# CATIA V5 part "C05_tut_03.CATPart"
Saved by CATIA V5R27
Part number: Part1
Bounding box of the stored display mesh (mm): x -75 to 75, y -149.983 to 149.983, z 0 to 150
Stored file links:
  E:\_Deepak\2017_Deepak\CATIA\Resources\Tutorial Files\Tutorials\c05_catia_v5_6r2016_tut\C05_tut_03.CATPart
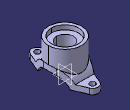
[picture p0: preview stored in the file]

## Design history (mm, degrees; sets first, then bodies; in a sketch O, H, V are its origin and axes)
Body1 (main body)
  Sketch1 on yz-plane, origin (0, 0, 0), H (0, 1, 0), V (0, 0, 1)
    point P1 (-150, 0)
    line L1 (-150, 0) -> (-74.162, 0)
    line L2 (150, 0) -> (150, 25)
    line L3 (150, 25) -> (89.4427, 25)
    line L4 (-150, 25) -> (-150, 0)
    point P2 (150, 0)
    arc A1 centre (0, -30) radius 80 from (74.162, 0) to (-74.162, 0) ccw
    point P5 (0, -30)
    arc A2 centre (0, -30) radius 105 from (89.4427, 25) to (-89.4427, 25) ccw
    line L5 (74.162, 0) -> (150, 0)
    line L6 (-89.4427, 25) -> (-150, 25)
    length L2 = 25
    distance V L4 = 150
    distance L1 P5 = 30
    radius A1 = 80
    radius A2 = 105
    distance P1 P2 = 300
    coincidence: P1 H, P5 V, L1 L5, L3 L6
    horizontal: L1 H, L3 H, L5 H, L6 H
    vertical: L2 V, L4 V
  Pad1: profile Sketch1, direction (1, 0, 0), length 75, mirrored extent
  Sketch2 on xy-plane, origin (0, 0, 0), H (1, 0, 0), V (0, 1, 0)
    arc A1 centre (0, 0) radius 75 from (-68.7386, 30) to (-68.7386, -30) ccw
    arc A2 centre (0, 125) radius 25 from (22.9129, 135) to (-22.9129, 135) ccw
    point P1 (0, 125)
    reference intersected line E1 through (0, 0) direction (-1, 0) from zx-plane
    arc A3 centre (0, -125) radius 25 from (22.9129, -135) to (-22.9129, -135) cw
    line L1 (-22.9129, 135) -> (-68.7386, 30)
    line L2 (22.9129, 135) -> (68.7386, 30)
    line L3 (-68.7386, -30) -> (-22.9129, -135)
    line L4 (22.9129, -135) -> (68.7386, -30)
    point P12 (68.7386, -30)
    arc A4 centre (0, 0) radius 75 from (68.7386, -30) to (68.7386, 30) ccw
    reference projected line E2 (-75, 89.4427) -> (-75, -89.4427) from edge [start face of Pad1 | face of Pad1 from Sketch1.A2]
    reference projected line E3 (-75, 150) -> (75, 150) from edge [face of Pad1 from Sketch1.L3 | face of Pad1 from Sketch1.L2]
    radius A2 = 25
    coincidence: P1 V, A1 P12, A1 A4
    symmetry: A2 A3 E1
    tangency: L1 A2, L1 A1, L2 A2, L2 A1, L3 A1, L3 A3, L4 A3, L4 A1, A1 E2, A2 E3
  Pocket1: profile Sketch2, direction (0, 0, -1), length 83, mirrored extent, outer side
  Plane1: type Offset, RefPlane xy-plane, Offset 150
  Sketch3 on Plane1, origin (0, 0, 150), H (1, 0, 0), V (0, 1, 0)
    circle A1 centre (0, 0) radius 75
    radius A1 = 75
  Pad2: profile Sketch3, direction (0, 0, 1), up to face of Pad1 from Sketch1.A2
  Sketch4 on yz-plane, origin (0, 0, 0), H (0, 1, 0), V (0, 0, 1)
    point P1 (0, 150)
    line L1 (0, 150) -> (0, 0)
    line L2 (0, 0) -> (37.5, 0)
    line L3 (37.5, 0) -> (37.5, 130)
    line L4 (37.5, 130) -> (61.5, 130)
    line L5 (61.5, 130) -> (61.5, 150)
    line L6 (61.5, 150) -> (0, 150)
    reference projected line E1 (-75, 150) -> (75, 150) from edge [face of Pad2 from Sketch3.A1 | start face of Pad2]
    axis line L7 (0, 209.2639) -> (0, 0)
    point P7 (0, 209.2639)
    length L5 = 20
    radius about axis L5 L7 = 61.5
    radius about axis L7 L3 = 37.5
    coincidence: P1 V, L6 E1, P7 V, L2 H
    vertical: L1 V, L5 V, L3 V, L7 V
    horizontal: L2 H, L4 H, L6 H
  Groove1: profile Sketch4, axis Sketch4.L7, angle 360
  Sketch5 on xy-plane, origin (0, 0, 0), H (1, 0, 0), V (0, 1, 0)
    circle A1 centre (0, 125) radius 12.5
    point P1 (0, 125)
    reference intersected line E1 through (0, 0) direction (-1, 0) from zx-plane
    circle A2 centre (0, -125) radius 12.5
    reference projected arc E2 centre (0, 125) radius 25 from (22.9129, 135) to (-22.9129, 135) ccw from edge [face of Pocket1 | face of Pad1 from Sketch1.L3]
    radius A1 = 12.5
    coincidence: P1 V
    symmetry: A1 A2 E1
    concentricity: A1 E2
  Pocket2: profile Sketch5, direction (0, 0, -1), through (limit type 3)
